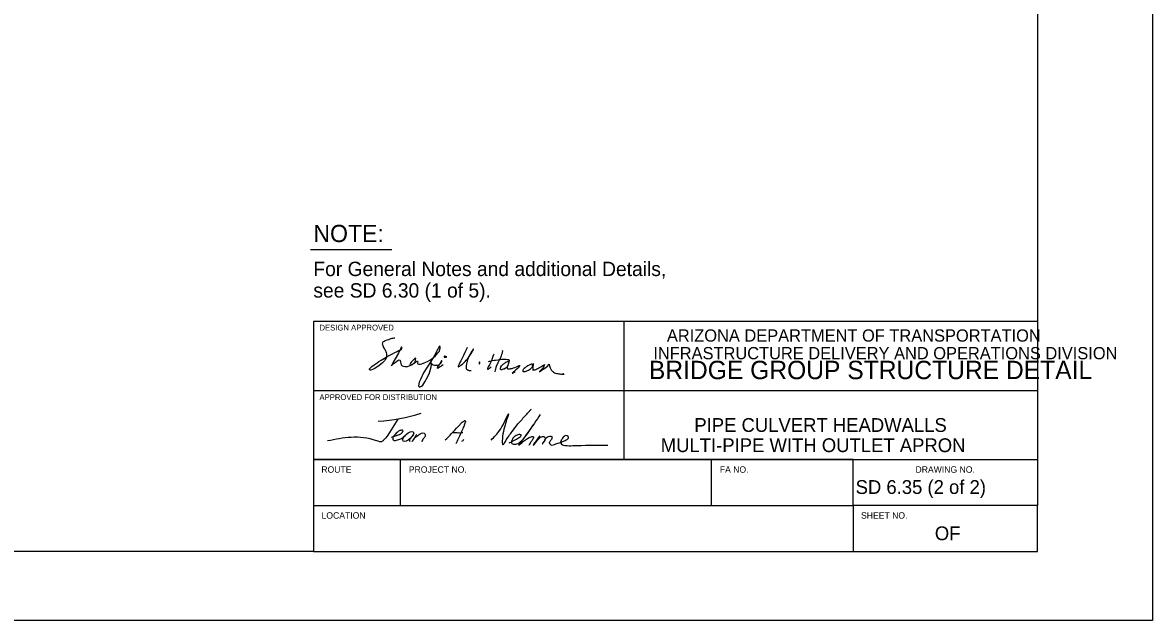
# Model space of a CAD drawing. Extents: x -0.08 to 2.83, y -0.03 to 1.92.
# Drawn here: x 1.811 to 2.833, y 0 to 0.542 of the extents above; entities that cross this region are included whole.
import ezdxf

# ---------------------------------------------------------------- set-up
doc = ezdxf.new("R2010")
doc.units = 0
for name, color, linetype in [('55', 7, 'Continuous'), ('57', 7, 'Continuous'), ('62', 7, 'Continuous'), ('63', 7, 'Continuous')]:
    doc.layers.add(name, color=color, linetype=linetype)

msp = doc.modelspace()

# ---------------------------------------------------------------- linework, layer by layer
at = {"layer": '57'}
msp.add_line((2.0713, 0.3361), (2.1448, 0.3361), dxfattribs=at)
for points in [[(2.1477, 0.2556), (2.1468, 0.2557), (2.1458, 0.2554), (2.1449, 0.2553), (2.144, 0.255), (2.1431, 0.2548), (2.142, 0.2543), (2.1404, 0.2539), (2.139, 0.2533), (2.1381, 0.2528), (2.1376, 0.2526), (2.1371, 0.2524), (2.1366, 0.2519), (2.1364, 0.2514), (2.1363, 0.2504), (2.1365, 0.2499), (2.1367, 0.2491), (2.1371, 0.2482), (2.1375, 0.2473), (2.138, 0.2463), (2.1385, 0.2457), (2.1391, 0.2444), (2.1395, 0.2436), (2.1399, 0.2429), (2.1401, 0.2414), (2.1402, 0.2405), (2.1401, 0.2395), (2.1397, 0.238), (2.1389, 0.2363), (2.1382, 0.2352), (2.1366, 0.2333), (2.1351, 0.2323), (2.1333, 0.2307), (2.1317, 0.2297), (2.1303, 0.2288), (2.1288, 0.228), (2.1273, 0.2273), (2.1258, 0.2268), (2.125, 0.2269), (2.1246, 0.2276), (2.1248, 0.228), (2.1254, 0.2285), (2.1258, 0.2291), (2.1269, 0.23), (2.129, 0.2315), (2.1299, 0.2322), (2.1315, 0.2334), (2.1333, 0.2345), (2.1352, 0.2357), (2.1368, 0.2366), (2.1413, 0.2395), (2.1456, 0.2416), (2.1476, 0.2427), (2.1498, 0.2437), (2.1514, 0.2445), (2.1527, 0.2452), (2.1536, 0.2459), (2.154, 0.2465), (2.154, 0.2477), (2.1536, 0.2479), (2.1534, 0.2477), (2.1533, 0.2474), (2.1519, 0.2441), (2.151, 0.2423), (2.1479, 0.2371), (2.1462, 0.2339), (2.1454, 0.2326), (2.1446, 0.2309), (2.1447, 0.2307), (2.1462, 0.2324), (2.1479, 0.2338), (2.1493, 0.2349), (2.1504, 0.2355), (2.1503, 0.2355), (2.1517, 0.236), (2.1523, 0.2358), (2.1525, 0.2355), (2.1529, 0.2341), (2.153, 0.2328), (2.1535, 0.2316), (2.1542, 0.2306), (2.1566, 0.2301), (2.159, 0.2301), (2.1606, 0.2308), (2.1633, 0.2318), (2.1649, 0.233), (2.1659, 0.2341), (2.1662, 0.2362), (2.1665, 0.2374), (2.1662, 0.2377), (2.1657, 0.2374), (2.1644, 0.2361), (2.163, 0.2346), (2.1624, 0.234), (2.1617, 0.2332), (2.1613, 0.2319), (2.1615, 0.2311), (2.1631, 0.2319), (2.165, 0.2331), (2.1666, 0.2342), (2.1675, 0.2349)], [(2.1675, 0.2349), (2.1677, 0.235), (2.168, 0.235), (2.1683, 0.2343), (2.1681, 0.2332), (2.1685, 0.2325), (2.1694, 0.2323), (2.1707, 0.2323), (2.1722, 0.2326), (2.1743, 0.2334), (2.1771, 0.2347), (2.1792, 0.2359), (2.1811, 0.237), (2.184, 0.2394), (2.1867, 0.2425), (2.1874, 0.2434), (2.188, 0.2441), (2.1888, 0.2468), (2.1886, 0.2482), (2.188, 0.2484), (2.1852, 0.2437), (2.1836, 0.2401), (2.1786, 0.2322), (2.1764, 0.2285), (2.1737, 0.2244), (2.1708, 0.2182), (2.1698, 0.2158), (2.1692, 0.2126), (2.1693, 0.2119), (2.1701, 0.2114), (2.1719, 0.2123), (2.173, 0.2133), (2.1749, 0.2161), (2.1775, 0.2209), (2.1789, 0.2242), (2.1797, 0.2265), (2.1806, 0.2298), (2.1808, 0.2318), (2.1807, 0.2332), (2.1801, 0.2336), (2.1797, 0.2338), (2.18, 0.2331), (2.1807, 0.2327), (2.1813, 0.2322), (2.1824, 0.2317), (2.1835, 0.2313), (2.1841, 0.2313), (2.1858, 0.2312), (2.1865, 0.2313), (2.1879, 0.2317), (2.1891, 0.2327), (2.1894, 0.233), (2.1901, 0.2346), (2.1902, 0.2351), (2.1898, 0.2354), (2.1884, 0.2324), (2.1867, 0.2305), (2.1863, 0.2297), (2.186, 0.229), (2.1862, 0.2285), (2.1886, 0.23), (2.1895, 0.2305), (2.1906, 0.2312), (2.1914, 0.2318)], [(2.2132, 0.2473), (2.2128, 0.2463), (2.2119, 0.2446), (2.2111, 0.2429), (2.2099, 0.24), (2.2092, 0.2388), (2.2084, 0.2371), (2.2075, 0.2353), (2.2066, 0.2336), (2.2059, 0.2321), (2.2052, 0.2309), (2.205, 0.2303), (2.205, 0.23), (2.2051, 0.2299), (2.2054, 0.2298), (2.2057, 0.23), (2.2065, 0.2305), (2.2074, 0.2312), (2.2088, 0.2323), (2.2101, 0.2334), (2.2113, 0.2347), (2.2122, 0.2357), (2.2133, 0.2367), (2.214, 0.2375), (2.2148, 0.239), (2.216, 0.2409), (2.2167, 0.242), (2.2178, 0.2441), (2.2184, 0.2448), (2.2189, 0.2456), (2.2189, 0.2458), (2.2188, 0.2459), (2.2187, 0.246), (2.2185, 0.2459), (2.2181, 0.2452), (2.2172, 0.2441), (2.216, 0.242), (2.2157, 0.2413), (2.2153, 0.2404), (2.2149, 0.2396), (2.2139, 0.2375), (2.2133, 0.236), (2.213, 0.2348), (2.2127, 0.2337), (2.2125, 0.2324), (2.2123, 0.2307), (2.2122, 0.2295), (2.2123, 0.2283), (2.2126, 0.2278), (2.2132, 0.2273), (2.2138, 0.2269), (2.2143, 0.2267), (2.215, 0.2265), (2.2156, 0.2264), (2.2162, 0.2264), (2.2167, 0.2264)], [(2.1947, 0.2388), (2.1943, 0.2388), (2.1938, 0.2389), (2.1934, 0.2391), (2.1931, 0.2393), (2.1928, 0.2393), (2.1925, 0.2393), (2.1924, 0.2392), (2.1922, 0.239), (2.1922, 0.2389), (2.1922, 0.2386), (2.1925, 0.2385), (2.1927, 0.2385), (2.193, 0.2385), (2.1935, 0.2386), (2.1938, 0.2386), (2.1942, 0.2386), (2.1946, 0.2387), (2.1947, 0.2387)], [(2.2371, 0.2412), (2.2367, 0.24), (2.2364, 0.239), (2.2358, 0.2372), (2.235, 0.2353), (2.2346, 0.2345), (2.2341, 0.2333), (2.2333, 0.2317), (2.2327, 0.2306), (2.2322, 0.2297), (2.2317, 0.2288), (2.2315, 0.2282), (2.2315, 0.2278), (2.2316, 0.2276), (2.2318, 0.2276), (2.232, 0.2276), (2.2326, 0.228), (2.2331, 0.2284), (2.2334, 0.2286), (2.2336, 0.2288), (2.2338, 0.2289), (2.234, 0.2291), (2.2342, 0.2293), (2.2344, 0.2295), (2.2345, 0.2296), (2.2347, 0.2298)], [(2.2325, 0.2346), (2.2332, 0.2348), (2.2342, 0.235), (2.2357, 0.2354), (2.2374, 0.2358), (2.2388, 0.2359), (2.2409, 0.2362), (2.243, 0.2364), (2.2448, 0.2366), (2.2463, 0.2366), (2.2475, 0.2366), (2.2482, 0.2366), (2.2495, 0.2365), (2.2505, 0.2364), (2.2509, 0.2362), (2.2511, 0.2357), (2.2507, 0.2337), (2.2506, 0.2334), (2.2501, 0.2318), (2.2497, 0.2308), (2.2492, 0.2298), (2.249, 0.2294), (2.2488, 0.2291), (2.2486, 0.2288), (2.2479, 0.2285), (2.2467, 0.2278), (2.2457, 0.2276), (2.2449, 0.2273), (2.2445, 0.2272), (2.244, 0.2272), (2.2435, 0.2274), (2.2433, 0.2275), (2.2433, 0.2277), (2.2433, 0.2281), (2.2433, 0.2288), (2.2435, 0.2293), (2.2437, 0.2298), (2.2441, 0.2306), (2.2447, 0.2312), (2.2456, 0.2321), (2.2463, 0.2326), (2.2468, 0.233), (2.2474, 0.2335), (2.2481, 0.2339), (2.249, 0.2344), (2.2496, 0.2347), (2.2503, 0.235), (2.2505, 0.235), (2.2508, 0.2349), (2.2508, 0.2347), (2.2506, 0.2334), (2.2505, 0.2332), (2.2503, 0.2322), (2.2499, 0.231), (2.2495, 0.23), (2.2494, 0.2295), (2.2494, 0.2293), (2.2493, 0.2291), (2.2493, 0.2287), (2.2494, 0.2284), (2.2498, 0.2281), (2.2499, 0.228), (2.2501, 0.228), (2.2505, 0.228), (2.2511, 0.228), (2.2515, 0.228), (2.2519, 0.2281), (2.2525, 0.2282), (2.2531, 0.2283), (2.2537, 0.2284), (2.2544, 0.2285), (2.2551, 0.2288), (2.2563, 0.2293), (2.2578, 0.2299), (2.2589, 0.2304), (2.2597, 0.2307), (2.2602, 0.231), (2.2608, 0.2311), (2.2609, 0.231), (2.2606, 0.2304), (2.26, 0.2298), (2.2593, 0.229), (2.2589, 0.2286), (2.2583, 0.228), (2.2572, 0.227), (2.2541, 0.2242), (2.2538, 0.224), (2.2541, 0.2241), (2.255, 0.2245), (2.2558, 0.2249), (2.2563, 0.2251), (2.2566, 0.2253)], [(2.2447, 0.2448), (2.245, 0.2443), (2.245, 0.2437), (2.2449, 0.2432), (2.2447, 0.2423), (2.2443, 0.2408), (2.2439, 0.2397), (2.2432, 0.238), (2.2427, 0.237), (2.2421, 0.2359), (2.241, 0.2334), (2.2406, 0.2326), (2.2395, 0.2304), (2.2393, 0.23), (2.239, 0.2291), (2.2386, 0.2277), (2.2384, 0.2267), (2.2382, 0.2256), (2.2381, 0.2252)], [(2.2244, 0.2324), (2.2247, 0.2331), (2.2246, 0.2338), (2.2244, 0.2341), (2.2241, 0.2341), (2.224, 0.2339), (2.2239, 0.2332), (2.224, 0.2326), (2.2242, 0.2323), (2.2243, 0.2322), (2.2244, 0.2322), (2.2244, 0.2324)], [(2.2723, 0.2303), (2.2721, 0.2318), (2.2715, 0.2323), (2.271, 0.2321), (2.2692, 0.2314), (2.2681, 0.2308), (2.2672, 0.2302), (2.2664, 0.2297), (2.2655, 0.229), (2.2647, 0.2284), (2.2642, 0.2278), (2.2637, 0.2272), (2.2634, 0.2266), (2.2634, 0.2263), (2.2634, 0.2259), (2.2637, 0.2256), (2.264, 0.2255), (2.2644, 0.2254), (2.2646, 0.2254), (2.2652, 0.2255), (2.2655, 0.2256), (2.2664, 0.2258), (2.2678, 0.2263), (2.2686, 0.2269), (2.2695, 0.2275), (2.2703, 0.2281), (2.2711, 0.2287), (2.2718, 0.2294), (2.2724, 0.2301), (2.2731, 0.2315), (2.2732, 0.2322), (2.273, 0.2327), (2.2727, 0.2323), (2.2726, 0.2317), (2.2726, 0.231), (2.2726, 0.2299), (2.2726, 0.2291), (2.2726, 0.2283), (2.2726, 0.2277), (2.2726, 0.2269), (2.2727, 0.2267), (2.2728, 0.2267), (2.2737, 0.227), (2.2747, 0.2272), (2.2754, 0.2275), (2.2761, 0.2279), (2.2764, 0.228), (2.2772, 0.2284), (2.278, 0.2288), (2.2792, 0.2296), (2.2804, 0.2302), (2.2817, 0.2309), (2.2821, 0.2312), (2.283, 0.2318), (2.2831, 0.2317), (2.2829, 0.231), (2.2826, 0.2303), (2.2822, 0.2296), (2.2816, 0.2287), (2.2811, 0.2281), (2.2799, 0.2268), (2.2786, 0.2256), (2.2785, 0.2253), (2.2787, 0.2253), (2.2801, 0.2263), (2.2819, 0.2276), (2.2834, 0.2286), (2.2845, 0.2294), (2.2857, 0.2303), (2.287, 0.2318), (2.2871, 0.2318), (2.2873, 0.2321), (2.2874, 0.232), (2.2877, 0.2307), (2.2879, 0.2299), (2.2882, 0.229), (2.2885, 0.2284), (2.2888, 0.2277), (2.2891, 0.2271), (2.2896, 0.2263), (2.29, 0.2258), (2.2905, 0.2255), (2.2909, 0.2251), (2.2913, 0.2249), (2.2923, 0.2244), (2.2932, 0.2241), (2.2944, 0.2237), (2.2951, 0.2236), (2.2961, 0.2234), (2.297, 0.2233), (2.298, 0.2232), (2.2988, 0.2232), (2.2995, 0.2231), (2.3005, 0.223), (2.3009, 0.2229), (2.3007, 0.2231), (2.3004, 0.2233), (2.3001, 0.2235), (2.2999, 0.2236)]]:
    msp.add_lwpolyline(points, dxfattribs=at)
msp.add_arc((2.1258, 0.3265), 0.1461, 272.671, 288.185, dxfattribs=at)
msp.add_ellipse((2.1597, 0.1667), major_axis=(0.00445, 0.00414), ratio=0.425517, dxfattribs=at)
for points in [[(2.2347, 0.1633), (2.2425, 0.1721), (2.2468, 0.1799), (2.2506, 0.1869), (2.2498, 0.1845), (2.2487, 0.1817), (2.2479, 0.1785), (2.2459, 0.1712), (2.2458, 0.1593), (2.2477, 0.1622), (2.2538, 0.1711), (2.2591, 0.178), (2.2628, 0.1822), (2.2695, 0.1897), (2.2712, 0.1915)], [(2.2791, 0.1865), (2.2669, 0.1687), (2.26, 0.1588), (2.271, 0.1664), (2.2717, 0.1665), (2.2732, 0.1663), (2.2731, 0.1653), (2.2715, 0.1627), (2.269, 0.1586)], [(2.1503, 0.1825), (2.1375, 0.1632), (2.1366, 0.1623), (2.1312, 0.1628), (2.0868, 0.1626)], [(2.1932, 0.1635), (2.199, 0.1693), (2.205, 0.1757), (2.2072, 0.1782), (2.2094, 0.1803), (2.2114, 0.181), (2.2113, 0.1794), (2.2108, 0.1779), (2.2091, 0.1736), (2.205, 0.1646), (2.2028, 0.16)], [(2.251, 0.1608), (2.2596, 0.1653), (2.261, 0.1663), (2.262, 0.1678), (2.2617, 0.1682), (2.26, 0.1684), (2.2567, 0.1671), (2.254, 0.1642), (2.2533, 0.162), (2.2533, 0.161), (2.2558, 0.1596), (2.2601, 0.1609), (2.2641, 0.1646), (2.2731, 0.1773)], [(2.1447, 0.166), (2.1519, 0.1686), (2.154, 0.1699), (2.155, 0.1715), (2.155, 0.1722), (2.1537, 0.1723), (2.1511, 0.1715), (2.1483, 0.1689), (2.1465, 0.1668), (2.1457, 0.1646), (2.1463, 0.1633), (2.1491, 0.1632), (2.153, 0.1646), (2.1551, 0.1658), (2.1571, 0.1674), (2.1572, 0.1674)], [(2.1642, 0.1709), (2.1647, 0.1696), (2.1632, 0.1667), (2.1612, 0.1643), (2.1608, 0.1628), (2.1615, 0.1621)], [(2.1673, 0.1685), (2.1658, 0.1661), (2.1634, 0.1622), (2.1659, 0.1656), (2.1691, 0.168), (2.1705, 0.169), (2.1749, 0.1692), (2.1752, 0.1678), (2.1748, 0.1663), (2.1729, 0.1639), (2.172, 0.1618)], [(2.2002, 0.1702), (2.2027, 0.1703), (2.2053, 0.1701), (2.2092, 0.1703)], [(2.2099, 0.1638), (2.2091, 0.1627), (2.2081, 0.162)], [(2.2788, 0.1674), (2.2734, 0.1591), (2.2738, 0.1595), (2.2796, 0.1659), (2.2814, 0.1666), (2.2834, 0.166), (2.2837, 0.1642), (2.2827, 0.1623), (2.2811, 0.1599), (2.2835, 0.1633), (2.2855, 0.166), (2.2896, 0.1665), (2.2894, 0.164), (2.2876, 0.1603), (2.288, 0.1599), (2.2888, 0.1592), (2.2935, 0.1599), (2.2997, 0.162), (2.3027, 0.1636), (2.3049, 0.1657), (2.3035, 0.1673), (2.3, 0.1659), (2.2983, 0.1632), (2.2979, 0.1623), (2.2978, 0.1605), (2.3016, 0.1586), (2.3087, 0.1584), (2.3405, 0.1588)]]:
    msp.add_spline(points, degree=3, dxfattribs=at)
at = {"layer": '63'}
for p, q in [((2.8333, 1.8333), (2.8333, 0)), ((2.7292, 0.2708), (2.0739, 0.2708)), ((2.0739, 0.2708), (2.0739, 0.0624)), ((2.3549, 0.2708), (2.3549, 0.1458)), ((2.0739, 0.2083), (2.7292, 0.2083)), ((2.0739, 0.1458), (2.7292, 0.1458)), ((2.0739, 0.144), (2.0739, 0.144)), ((2.0891, 0.1458), (2.0893, 0.1458)), ((2.1527, 0.1041), (2.1527, 0.1458)), ((2.4343, 0.1041), (2.4343, 0.1458)), ((2.0739, 0.1041), (2.5625, 0.1041)), ((2.5625, 0.1041), (2.5625, 0.0624)), ((2.7292, 0.0624), (2.7292, 0.1041)), ((2.0739, 0.0624), (2.7292, 0.0624)), ((2.8333, 0), (0, 0)), ((2.83, 0.0003), (2.83, 0.0003))]:
    msp.add_line(p, q, dxfattribs=at)
msp.add_lwpolyline([(0.1667, 0.0624), (0.1667, 1.7708), (2.7292, 1.7708), (2.7292, 0.1041), (2.5625, 0.1041), (2.5625, 0.1458), (2.0739, 0.1458), (2.0739, 0.0624)], close=True, dxfattribs=at)

# ---------------------------------------------------------------- texts
at = {"layer": '55'}
for s, p in [('DESIGN APPROVED', (2.0794, 0.2627)), ('APPROVED FOR DISTRIBUTION', (2.0794, 0.1997))]:
    msp.add_text(s, height=0.005208, dxfattribs=at).set_placement(p)
at = {"layer": '57'}
for s, height, p in [('NOTE:', 0.01562, (2.0739, 0.3428)), ('For General Notes and additional Details,', 0.013021, (2.0739, 0.312)), ('see SD 6.30 (1 of 5).', 0.013021, (2.0739, 0.2925))]:
    msp.add_text(s, height=height, dxfattribs=at).set_placement(p)
at = {"layer": '62'}
for s, p in [('PIPE CULVERT HEADWALLS', (2.4187, 0.1708)), ('MULTI-PIPE WITH OUTLET APRON', (2.3883, 0.1525)), ('SD 6.35 (2 of 2)', (2.5647, 0.1146))]:
    msp.add_text(s, height=0.0125, dxfattribs=at).set_placement(p)
at = {"layer": '63'}
for s, height, p in [('ARIZONA DEPARTMENT OF TRANSPORTATION', 0.011108, (2.3939, 0.2526)), ('INFRASTRUCTURE DELIVERY AND OPERATIONS DIVISION', 0.011108, (2.3816, 0.2366)), ('BRIDGE GROUP STRUCTURE DETAIL', 0.016667, (2.3776, 0.2186)), ('ROUTE', 0.00583, (2.0811, 0.1338)), ('PROJECT NO.', 0.005833, (2.1603, 0.1338)), ('FA NO.', 0.00583, (2.4418, 0.1338)), ('DRAWING NO.', 0.005833, (2.6189, 0.1338)), ('LOCATION', 0.00583, (2.0813, 0.0922)), ('SHEET NO.', 0.00583, (2.5696, 0.0922)), ('OF', 0.0125, (2.6364, 0.0727))]:
    msp.add_text(s, height=height, dxfattribs=at).set_placement(p)

doc.saveas('drawing.dxf')
